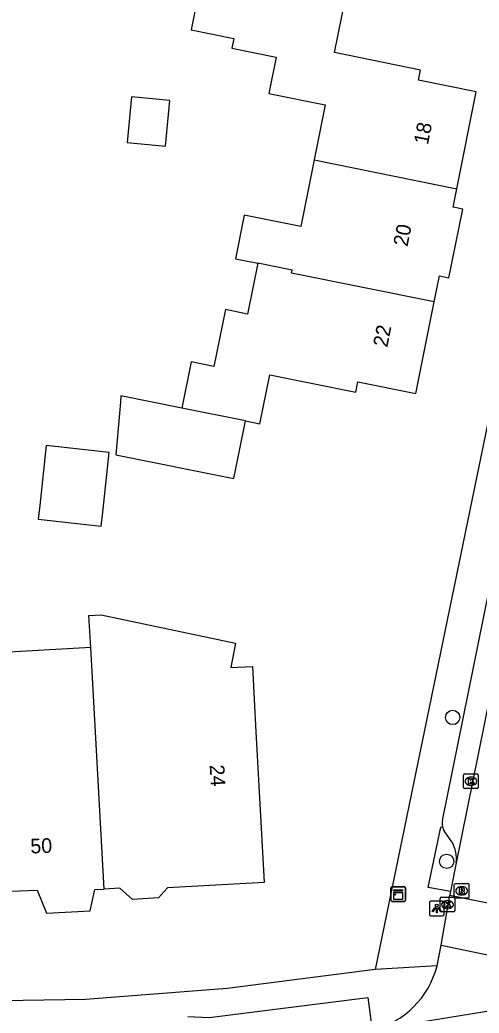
# Model space of a CAD drawing. Extents: x 161772 to 163123, y 383092 to 383917.
# Drawn here: x 162204.2 to 162235.6, y 383625.5 to 383693.3 of the extents above; entities that cross this region are included whole.
import ezdxf

# ---------------------------------------------------------------- set-up
doc = ezdxf.new("R2010")
doc.units = 0
for name, color, linetype in [('IMGEO_Boom', 7, 'Continuous'), ('IMGEO_Kast', 7, 'Continuous'), ('IMGEO_Kolk', 7, 'Continuous'), ('IMGEO_Lichtpunt', 7, 'Continuous'), ('IMGEO_Pand', 7, 'Continuous'), ('IMGEO_Pand_nummerreeks', 7, 'Continuous'), ('IMGEO_Parkeervlak_open', 7, 'Continuous'), ('IMGEO_Rijbaan_lokaal_gesloten', 7, 'Continuous'), ('IMGEO_Rijbaan_lokaal_open', 7, 'Continuous'), ('IMGEO_Rioolput', 7, 'Continuous'), ('IMGEO_Voetpad_open', 7, 'Continuous')]:
    doc.layers.add(name, color=color, linetype=linetype)

msp = doc.modelspace()

# ---------------------------------------------------------------- linework, layer by layer
at = {"layer": 'IMGEO_Boom'}
for centre in [(162233.775, 383645.707), (162233.364, 383635.888)]:
    msp.add_circle(centre, 0.489, dxfattribs=at)
at = {"layer": 'IMGEO_Kast'}
for p, q in [((162229.562, 383633.23), (162229.562, 383634.071)), ((162229.562, 383634.071), (162229.562, 383633.23)), ((162229.637, 383634.155), (162230.478, 383634.155)), ((162230.478, 383634.155), (162229.637, 383634.155)), ((162230.562, 383634.08), (162230.562, 383633.239)), ((162230.562, 383633.239), (162230.562, 383634.08)), ((162230.487, 383633.155), (162229.646, 383633.155)), ((162229.646, 383633.155), (162230.487, 383633.155))]:
    msp.add_line(p, q, dxfattribs=at)
for points in [[(162229.757, 383633.945), (162230.357, 383633.945), (162230.357, 383633.86), (162229.757, 383633.86), (162229.757, 383633.945)], [(162229.757, 383633.77), (162230.357, 383633.77), (162230.357, 383633.281), (162229.757, 383633.281), (162229.757, 383633.77)]]:
    msp.add_lwpolyline(points, dxfattribs=at)
msp.add_circle((162229.841, 383633.619), 0.0377, dxfattribs=at)
for centre, start, end in [((162229.64, 383634.077), 92.4484, 184.28452), ((162229.64, 383634.077), 92.4484, 184.28452), ((162230.484, 383634.077), 2.4484, 94.28452), ((162230.484, 383634.077), 2.4484, 94.28452), ((162229.64, 383633.233), 182.4484, 274.28452), ((162229.64, 383633.233), 182.4484, 274.28452), ((162230.484, 383633.233), 272.4484, 4.28452), ((162230.484, 383633.233), 272.4484, 4.28452)]:
    msp.add_arc(centre, 0.0779, start, end, dxfattribs=at)
at = {"layer": 'IMGEO_Kolk'}
for p, q in [((162234.521, 383640.925), (162234.521, 383641.777)), ((162234.596, 383641.851), (162235.448, 383641.851)), ((162235.009, 383641.631), (162235.034, 383641.631)), ((162235.522, 383641.777), (162235.522, 383640.925)), ((162235.448, 383640.851), (162234.596, 383640.851)), ((162235.032, 383641.071), (162235.007, 383641.071)), ((162232.918, 383632.506), (162232.918, 383633.358)), ((162232.993, 383633.432), (162233.845, 383633.432)), ((162233.406, 383633.212), (162233.431, 383633.212)), ((162233.919, 383633.358), (162233.919, 383632.506)), ((162233.429, 383632.652), (162233.404, 383632.652)), ((162233.845, 383632.432), (162232.993, 383632.432))]:
    msp.add_line(p, q, dxfattribs=at)
for points in [[(162234.521, 383640.925), (162234.521, 383641.777)], [(162234.596, 383641.851), (162235.448, 383641.851)], [(162234.842, 383641.551), (162234.965, 383641.551), (162234.965, 383641.4), (162235.095, 383641.551), (162235.259, 383641.551), (162235.113, 383641.4), (162235.266, 383641.151), (162235.114, 383641.151), (162235.029, 383641.315), (162234.965, 383641.248), (162234.965, 383641.151), (162234.842, 383641.151), (162234.842, 383641.551)], [(162235.522, 383641.777), (162235.522, 383640.925)], [(162235.448, 383640.851), (162234.596, 383640.851)], [(162232.918, 383632.506), (162232.918, 383633.358)], [(162232.993, 383633.432), (162233.845, 383633.432)], [(162233.919, 383633.358), (162233.919, 383632.506)], [(162233.239, 383633.132), (162233.362, 383633.132), (162233.362, 383632.981), (162233.492, 383633.132), (162233.656, 383633.132), (162233.51, 383632.981), (162233.663, 383632.732), (162233.511, 383632.732), (162233.426, 383632.896), (162233.362, 383632.829), (162233.362, 383632.732), (162233.239, 383632.732), (162233.239, 383633.132)], [(162233.845, 383632.432), (162232.993, 383632.432)]]:
    msp.add_lwpolyline(points, dxfattribs=at)
for centre, start, end in [((162234.598, 383641.775), 91.55205, 178.44795), ((162234.598, 383641.775), 91.55205, 178.44795), ((162235.446, 383641.775), 1.55205, 88.44795), ((162235.446, 383641.775), 1.55205, 88.44795), ((162234.598, 383640.927), 181.55205, 268.44795), ((162234.598, 383640.927), 181.55205, 268.44795), ((162235.446, 383640.927), 271.55205, 358.44795), ((162235.446, 383640.927), 271.55205, 358.44795), ((162232.995, 383633.356), 91.55205, 178.44795), ((162232.995, 383633.356), 91.55205, 178.44795), ((162233.843, 383633.356), 1.55205, 88.44795), ((162233.843, 383633.356), 1.55205, 88.44795), ((162232.995, 383632.508), 181.55205, 268.44795), ((162232.995, 383632.508), 181.55205, 268.44795), ((162233.843, 383632.508), 271.55205, 358.44795), ((162233.843, 383632.508), 271.55205, 358.44795)]:
    msp.add_arc(centre, 0.0765, start, end, dxfattribs=at)
for centre, major_axis, ratio, start_param, end_param in [((162235.008, 383641.351), (-0.387, 0.002), 0.722429, 4.712389, 7.853982), ((162235.033, 383641.351), (-0.39, 0.002), 0.717154, 1.570796, 4.712389), ((162233.405, 383632.932), (-0.387, 0.002), 0.722429, 4.712389, 7.853982), ((162233.43, 383632.932), (-0.39, 0.002), 0.717154, 1.570796, 4.712389)]:
    msp.add_ellipse(centre, major_axis=major_axis, ratio=ratio, start_param=start_param, end_param=end_param, dxfattribs=at)
at = {"layer": 'IMGEO_Lichtpunt'}
for p, q in [((162232.186, 383633.073), (162232.186, 383632.266)), ((162232.186, 383633.073), (162232.186, 383632.266)), ((162233.088, 383633.168), (162232.28, 383633.168)), ((162233.088, 383633.168), (162232.28, 383633.168)), ((162233.182, 383632.266), (162233.182, 383633.073)), ((162233.182, 383632.266), (162233.182, 383633.073)), ((162232.28, 383632.172), (162233.088, 383632.172)), ((162232.28, 383632.172), (162233.088, 383632.172))]:
    msp.add_line(p, q, dxfattribs=at)
for points in [[(162232.56, 383632.737), (162232.599, 383632.709), (162232.411, 383632.447), (162232.373, 383632.474), (162232.56, 383632.737)], [(162232.662, 383632.689), (162232.709, 383632.689), (162232.709, 383632.367), (162232.662, 383632.367), (162232.662, 383632.689)], [(162232.772, 383632.709), (162232.81, 383632.736), (162232.997, 383632.474), (162232.958, 383632.446), (162232.772, 383632.709)]]:
    msp.add_lwpolyline(points, dxfattribs=at)
msp.add_circle((162232.685, 383632.871), 0.0994, dxfattribs=at)
for centre, start, end in [((162232.28, 383633.073), 90, 180), ((162232.28, 383633.073), 90, 180), ((162233.088, 383633.073), 0, 90), ((162233.088, 383633.073), 0, 90), ((162232.28, 383632.266), 180, 270), ((162232.28, 383632.266), 180, 270), ((162233.088, 383632.266), 270, 0), ((162233.088, 383632.266), 270, 360)]:
    msp.add_arc(centre, 0.0946, start, end, dxfattribs=at)
at = {"layer": 'IMGEO_Pand'}
for points in [[(162234.05, 383681.787), (162235.385, 383688.403), (162231.445, 383689.198), (162231.584, 383689.885), (162225.713, 383691.07), (162226.465, 383694.795), (162221.564, 383695.784), (162221.133, 383695.871), (162221.131, 383695.86), (162216.747, 383696.756), (162215.915, 383692.632), (162218.841, 383692.042), (162218.705, 383691.37), (162221.725, 383690.761), (162221.227, 383688.294), (162225.08, 383687.517), (162224.32, 383683.75)], [(162214.477, 383687.807), (162211.851, 383688.061), (162211.549, 383684.939), (162214.175, 383684.685), (162214.477, 383687.807)], [(162224.32, 383683.75), (162223.403, 383679.205), (162219.551, 383679.983), (162218.95, 383677.004), (162220.474, 383676.697)], [(162224.32, 383683.75), (162234.05, 383681.787)], [(162232.511, 383674.058), (162232.87, 383675.836), (162233.519, 383675.705), (162234.464, 383680.391), (162233.796, 383680.526), (162234.05, 383681.787)], [(162220.474, 383676.697), (162219.774, 383673.227), (162218.261, 383673.533), (162217.478, 383669.652), (162215.93, 383669.965), (162215.296, 383666.819)], [(162232.511, 383674.058), (162222.77, 383676.013), (162222.813, 383676.225), (162220.474, 383676.697)], [(162219.636, 383665.943), (162220.616, 383665.745), (162221.291, 383669.096), (162227.162, 383667.912), (162227.3, 383668.598), (162231.25, 383667.802), (162232.511, 383674.058)], [(162215.296, 383666.819), (162211.13, 383667.66), (162211.091, 383667.214), (162210.781, 383663.637), (162218.844, 383662.011), (162219.636, 383665.943)], [(162219.636, 383665.943), (162215.296, 383666.819)], [(162209.887, 383659.712), (162210.329, 383663.788), (162206.029, 383664.254), (162205.588, 383660.178), (162205.485, 383659.229), (162209.785, 383658.764), (162209.887, 383659.712)], [(162209.071, 383650.478), (162208.95, 383652.66), (162209.776, 383652.706), (162218.957, 383650.784), (162218.641, 383649.111), (162220.1, 383649.192), (162220.346, 383644.73), (162220.55, 383641.031), (162220.913, 383634.437), (162214.312, 383634.073), (162213.698, 383633.388), (162211.914, 383633.289), (162211.059, 383634.055), (162209.982, 383633.996)], [(162209.071, 383650.478), (162202.659, 383650.124), (162197.967, 383649.865), (162198.016, 383648.987), (162198.195, 383645.752), (162197.987, 383645.741), (162198.184, 383642.158), (162198.46, 383637.165), (162198.585, 383634.91)], [(162209.982, 383633.996), (162209.071, 383650.478)], [(162199.908, 383633.709), (162201.791, 383633.78), (162205.408, 383633.916), (162206.045, 383632.354), (162209.027, 383632.518), (162209.35, 383633.961), (162209.982, 383633.996)]]:
    msp.add_lwpolyline(points, dxfattribs=at)
at = {"layer": 'IMGEO_Parkeervlak_open'}
msp.add_lwpolyline([(162233.718, 383637.213), (162233.195, 383637.979)], dxfattribs=at)
for centre, radius, start, end in [((162233.929, 383638.468), 0.882, 194.00006, 213.69358), ((162231.902, 383636.105), 2.127, 351.34204, 31.38583)]:
    msp.add_arc(centre, radius, start, end, dxfattribs=at)
at = {"layer": 'IMGEO_Rijbaan_lokaal_gesloten'}
for points in [[(162232.711, 383628.765), (162232.978, 383630.162)], [(162242.808, 383626.724), (162228.274, 383624.366)]]:
    msp.add_lwpolyline(points, dxfattribs=at)
msp.add_arc((162226.828, 383630.262), 6.071, 283.78301, 345.72419, dxfattribs=at)
at = {"layer": 'IMGEO_Rijbaan_lokaal_open'}
for points in [[(162238.244, 383656.694), (162234.005, 383635.785)], [(162234.005, 383635.785), (162233.631, 383633.838)], [(162232.978, 383630.162), (162233.579, 383633.587)], [(162233.631, 383633.838), (162233.579, 383633.587)], [(162233.579, 383633.587), (162236.834, 383632.925)], [(162232.978, 383630.162), (162237.891, 383629.143)]]:
    msp.add_lwpolyline(points, dxfattribs=at)
at = {"layer": 'IMGEO_Rioolput'}
for p, q in [((162233.886, 383633.447), (162233.886, 383634.299)), ((162233.961, 383634.373), (162234.813, 383634.373)), ((162234.374, 383634.153), (162234.399, 383634.153)), ((162234.887, 383634.299), (162234.887, 383633.447)), ((162234.813, 383633.373), (162233.961, 383633.373)), ((162234.397, 383633.593), (162234.372, 383633.593))]:
    msp.add_line(p, q, dxfattribs=at)
for points in [[(162233.886, 383633.447), (162233.886, 383634.299)], [(162233.961, 383634.373), (162234.813, 383634.373)], [(162234.475, 383634.071), (162234.223, 383634.073), (162234.223, 383633.673)], [(162234.401, 383633.992), (162234.347, 383633.992), (162234.347, 383633.911)], [(162234.347, 383633.911), (162234.399, 383633.911)], [(162234.887, 383634.299), (162234.887, 383633.447)], [(162234.813, 383633.373), (162233.961, 383633.373)], [(162234.223, 383633.673), (162234.347, 383633.673), (162234.347, 383633.835), (162234.358, 383633.835)], [(162234.405, 383633.806), (162234.476, 383633.673), (162234.616, 383633.673), (162234.551, 383633.799)]]:
    msp.add_lwpolyline(points, dxfattribs=at)
for centre, radius, start, end in [((162233.963, 383634.297), 0.0765, 91.55205, 178.44795), ((162233.963, 383634.297), 0.0765, 91.55205, 178.44795), ((162234.383, 383634.1), 0.19, 274.7715, 282.96867), ((162234.407, 383633.896), 0.0964, 77.00612, 93.18647), ((162234.421, 383633.953), 0.0378, 276.66336, 79.67722), ((162234.474, 383633.961), 0.109, 350.36119, 89.41601), ((162234.472, 383633.961), 0.112, 277.58423, 350.98172), ((162234.811, 383634.297), 0.0765, 1.55205, 88.44795), ((162234.811, 383634.297), 0.0765, 1.55205, 88.44795), ((162233.963, 383633.449), 0.0765, 181.55205, 268.44795), ((162233.963, 383633.449), 0.0765, 181.55205, 268.44795), ((162234.357, 383633.782), 0.0533, 26.02933, 88.69889), ((162234.456, 383633.746), 0.108, 29.51342, 73.79051), ((162234.811, 383633.449), 0.0765, 271.55205, 358.44795), ((162234.811, 383633.449), 0.0765, 271.55205, 358.44795)]:
    msp.add_arc(centre, radius, start, end, dxfattribs=at)
for centre, major_axis, ratio, start_param, end_param in [((162234.373, 383633.873), (-0.387, 0.002), 0.722429, 4.712389, 7.853982), ((162234.398, 383633.873), (-0.39, 0.002), 0.717154, 1.570796, 4.712389)]:
    msp.add_ellipse(centre, major_axis=major_axis, ratio=ratio, start_param=start_param, end_param=end_param, dxfattribs=at)
at = {"layer": 'IMGEO_Voetpad_open'}
for points in [[(162259.685, 383782.554), (162253.133, 383750), (162236.634, 383668.028), (162228.473, 383628.501)], [(162233.079, 383638.681), (162236.258, 383654.397)], [(162233.631, 383633.838), (162232.092, 383634.108), (162232.967, 383638.221), (162233.073, 383638.255)], [(162228.473, 383628.501), (162218.379, 383627.215), (162208.722, 383626.465), (162198.753, 383626.298), (162198.74, 383626.03), (162198.361, 383626.093), (162198.383, 383626.312), (162194.823, 383626.159), (162194.801, 383625.929), (162192.525, 383626.242), (162189.607, 383626.341), (162189.516, 383626.162), (162188.5, 383626.178)], [(162232.711, 383628.765), (162228.473, 383628.501)], [(162215.695, 383625.293), (162217.142, 383625.229), (162227.986, 383626.586), (162228.274, 383624.366)]]:
    msp.add_lwpolyline(points, dxfattribs=at)
msp.add_arc((162233.903, 383638.456), 0.854, 164.74723, 193.63891, dxfattribs=at)

# ---------------------------------------------------------------- texts
at = {"layer": 'IMGEO_Pand_nummerreeks'}
for s, rotation, p in [('18', 78.64992, (162232.082, 383684.747)), ('20', 78.64992, (162230.685, 383677.791)), ('22', 78.64992, (162229.306, 383670.918)), ('24', 273.15106, (162217.186, 383642.459)), ('50', 2.15432, (162204.966, 383636.421))]:
    msp.add_text(s, height=1, rotation=rotation, dxfattribs=at).set_placement(p)

doc.saveas('drawing.dxf')
